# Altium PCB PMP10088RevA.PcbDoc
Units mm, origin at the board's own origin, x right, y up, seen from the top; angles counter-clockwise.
Board outline 78.74 x 52.07 mm, 2 copper layers (Top Layer, Bottom Layer), stack 1.575 mm thick; 38 components, 13 nets, 76 pads, 8 vias.
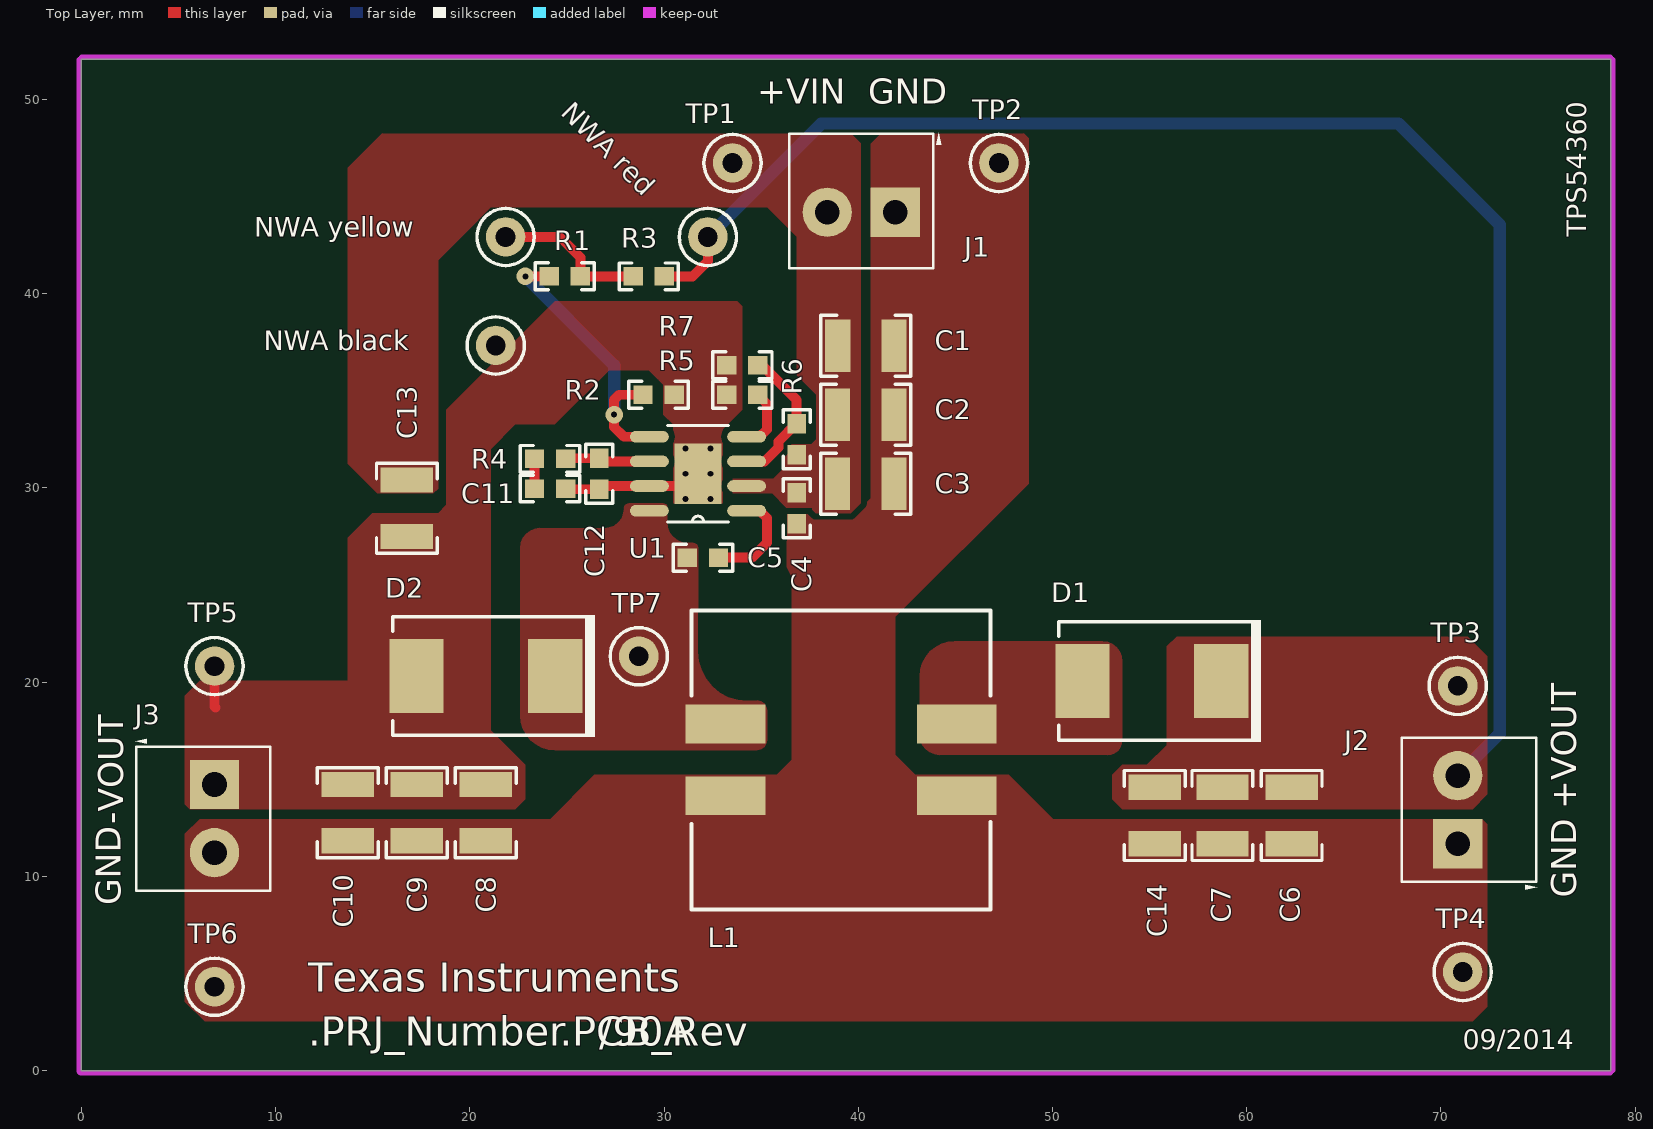
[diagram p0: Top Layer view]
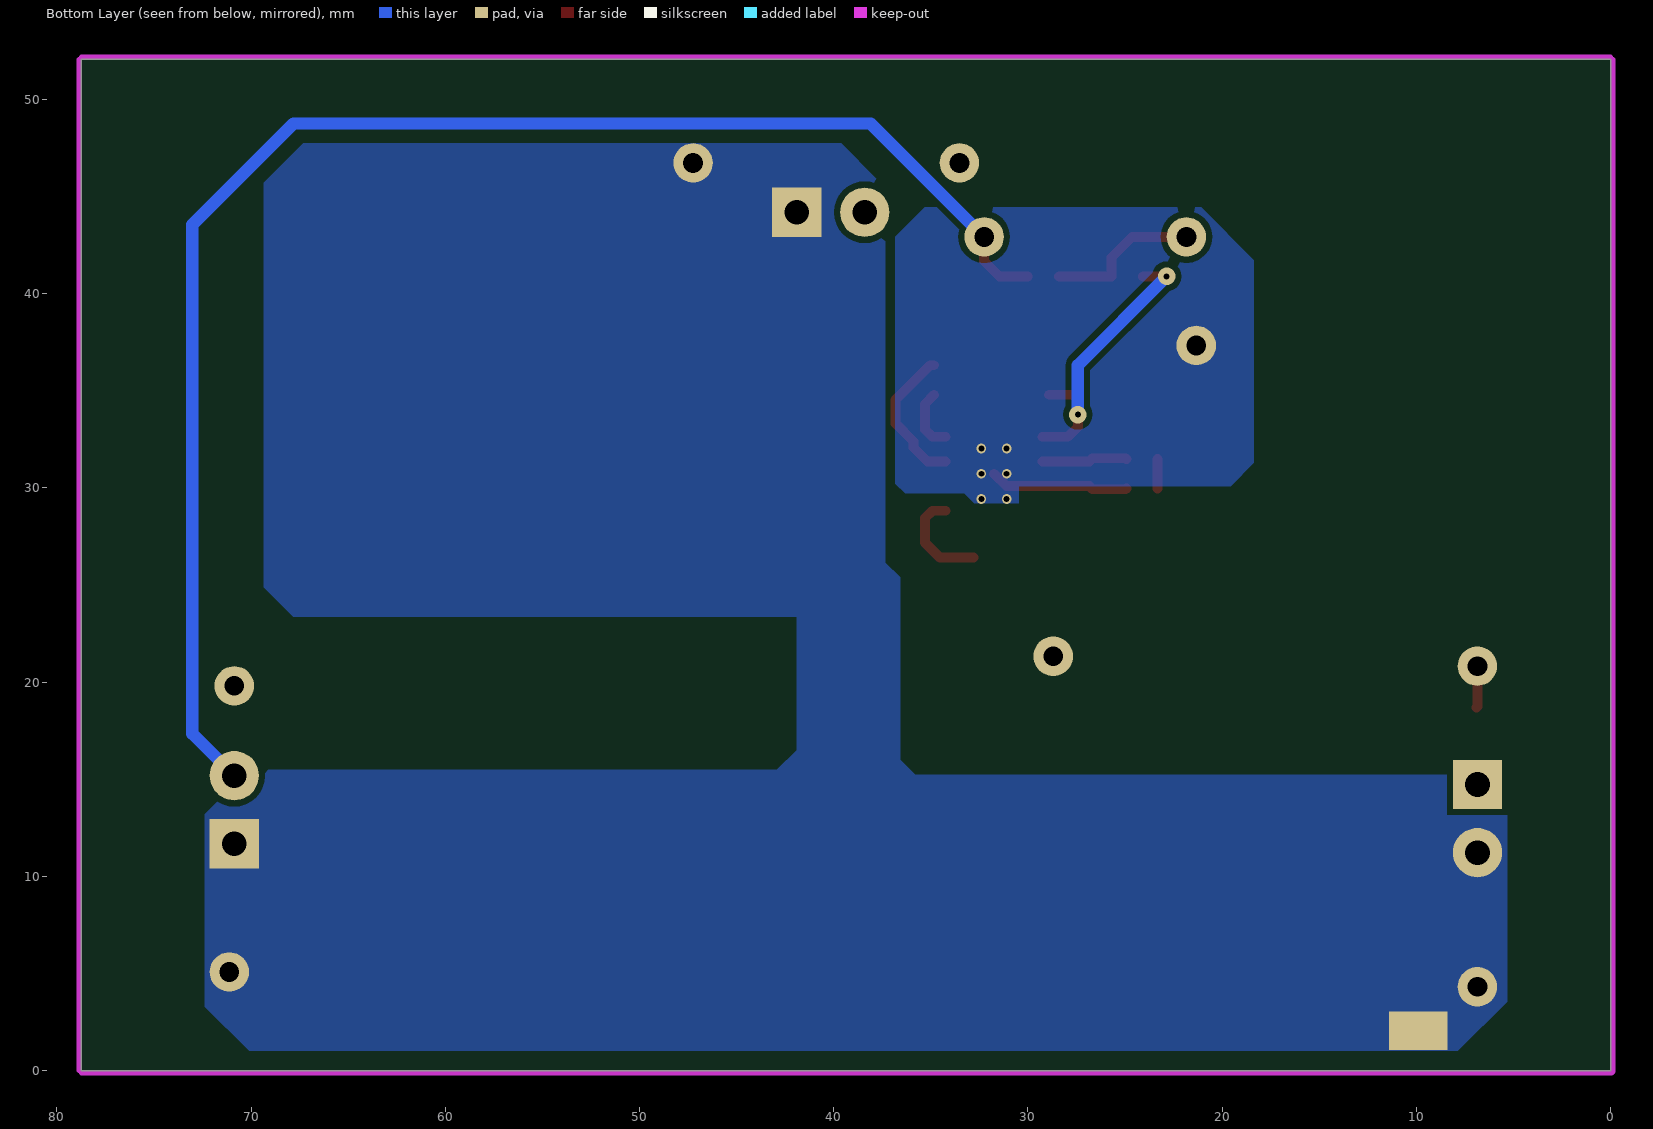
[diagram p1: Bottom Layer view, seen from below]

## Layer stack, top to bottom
Top Layer: signal copper 0.0356
Dielectric: core 1.5037, FR-4, Dk 4.8
Bottom Layer: signal copper 0.0356

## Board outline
0,0 78.74,0 78.74,52.07 0,52.07

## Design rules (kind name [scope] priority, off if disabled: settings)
AcuteAngle [All] p1: minimum=4.50000000000000E+0001 checktracksonly=FALSE
AssemblyTestPointUsage [All] p1: valid=2
Clearance Clearance_BoardEdge_MountingHoles [OnCopper and InComponentClass('Mounting Holes') vs IsKeepOut] p1: gap=1.016
Clearance Clearance_BoardEdge_Poly [OnCopper and InPoly vs IsKeepOut] p2: gap=0.635
Clearance Clearance_BoardEdge [OnCopper and Not InComponentClass('Logo') and not InComponentClass('FiducialMark') and not InRegion(1000,500,4000,800) and Not IsKeepout vs IsKeepOut] p3: gap=1
Clearance Clearance_Poly [InPolygon] p4: gap=0.32
Clearance [All] p5: gap=0.203
ComponentClearance ComponentClearance_Shunt [InComponentClass('Header') vs InComponentClass('Shunt')] p1: gap=0 collisioncheckmode=3 verticalgap=0 showdistances=FALSE
ComponentClearance ComponentClearance_Logo [InComponentClass('Logo')] p2: gap=1.27 collisioncheckmode=3 verticalgap=0.254 showdistances=FALSE
ComponentClearance ComponentClearance_ScrewToNut [(HasFootprint('NY PMS 440 0025 PH')) vs (HasFootprint('Keystone_1902C'))] p3: gap=0.127 collisioncheckmode=3 verticalgap=0.254 showdistances=FALSE
ComponentClearance ComponentClearance_MountingHoles [InComponentClass('Mounting Holes')] p4: gap=6.35 collisioncheckmode=3 verticalgap=2540 showdistances=FALSE
ComponentClearance ComponentClearance_SmallPassives [HasFootprint('0201*') or HasFootprint('0402*') or HasFootprint('0508') or HasFootprint('0603*') or HasFootprint('0612') or HasFootprint('0805*') or HasFootprint('0815*') or HasFootprint('0830*') or HasFootprint('1206*') or HasFootprint('1210*') or HasFootprint('1808*') or HasFootprint('1812*') or HasFootprint('1825*') or HasFootprint('2010*') or HasFootprint('2220*') or HasFootprint('2225*') or HasFootprint('2512*') or HasFootprint('2728*') or HasFootprint('3518*') vs HasFootprint('0201*') or HasFootprint('0402*') or HasFootprint('0508') or HasFootprint('0603*') or HasFootprint('0612') or HasFootprint('0805*') or HasFootprint('0815*') or HasFootprint('0830*') or HasFootprint('1206*') or HasFootprint('1210*') or HasFootprint('1808*') or HasFootprint('1812*') or HasFootprint('1825*') or HasFootprint('2010*') or HasFootprint('2220*') or HasFootprint('2225*') or HasFootprint('2512*') or HasFootprint('2728*') or HasFootprint('3518*')] p5: gap=0.508 collisioncheckmode=3 verticalgap=0.254 showdistances=FALSE
ComponentClearance ComponentClearance_THtoSMT [IsThruComponent vs IsSMTComponent] p6: gap=1.27 collisioncheckmode=3 verticalgap=0.762 showdistances=FALSE
ComponentClearance ComponentClearance_THtoTH [IsThruComponent vs IsThruComponent] p7: gap=1.5 collisioncheckmode=3 verticalgap=0.762 showdistances=FALSE
ComponentClearance [All] p8: gap=1.016 collisioncheckmode=3 verticalgap=0.254 showdistances=FALSE
DiffPairsRouting [All] p1: maxlimit=2.54 minlimit=0.254 mostfreqgap=0.254 maxuncoupledlength=25.4
FabricationTestPointUsage TestPointUsage [All] p1: valid=2 allowmultiple=FALSE
FabricationTestpoint Testpoint [All] p1: side=3 testpointundercomponent=TRUE minsize=1.016 maxsize=2.54 preferedsize=1.524 minholesize=0 maxholesize=1.016 preferedholesize=0.813 testpointgrid=0.025 allowsidetop=TRUE allowsidebottom=TRUE usegrid=TRUE gridtolerance=0
FanoutControl Fanout_LCC [IsLCC] p1: bgadir=Out bgaviamode=Centered fanoutstyle=Auto fanoutdirection=Alternating viagrid=0.025 // Fanout_LCC (Default Rule)
FanoutControl Fanout_BGA [IsBGA] p2: bgadir=Out bgaviamode=Centered fanoutstyle=Auto fanoutdirection=Alternating viagrid=0.025 // Fanout_BGA (Default Rule)
FanoutControl Fanout_Default [All] p4: bgadir=Out bgaviamode=Centered fanoutstyle=Auto fanoutdirection=Alternating viagrid=0.025 // Fanout_Default (Default Rule)
FanoutControl Fanout_Small [(CompPinCount < 5)] p5: bgadir=Out bgaviamode=Centered fanoutstyle=Auto fanoutdirection=OutThenIn viagrid=0.025 // Fanout_Small (Default Rule)
HoleSize [All] p1: absolutevalues=TRUE maxlimit=6.375 minlimit=0.3 maxpercent=80.000 minpercent=20.000
MinimumAnnularRing MinimumAnnularRing_ThermalPadVias [IsVia and InAnyComponent] p1: minimumring=0.15
MinimumAnnularRing [All] p2: minimumring=0.2
MinimumSolderMaskSliver MinimumSolderMaskSliver_Logo [InComponentClass('Logo') vs InComponentClass('Logo')] p1: minsoldermaskwidth=0.018
MinimumSolderMaskSliver [All] p2: minsoldermaskwidth=0.1
PlaneConnect [All] p1: planeconnectstyle=Relief reliefexpansion=0.254 reliefentries=4 reliefconductorwidth=0.254 reliefairgap=0.254
PolygonConnect [All] p1: connectstyle=Direct reliefconductorwidth=0.254 reliefentries=4 polygonreliefangle="90 Angle" airgapwidth=0.254
RoutingVias ThermalPadVias [IsVia and InAnyComponent] p1: holewidth=0.2 width=0.5 viastyle="Through Hole" minholewidth=0.3 minwidth=0.5 maxholewidth=0.33 maxwidth=0.6
RoutingVias [All] p2: holewidth=0.406 width=0.864 viastyle="Through Hole" minholewidth=0.3 minwidth=0.66 maxholewidth=1.016 maxwidth=1.651
SMDToCorner [All] p1: distance=30000
SilkToSilkClearance [All] p1: silktosilkclearance=0.127
SilkscreenOverComponentPads [All] p1: minsilkscreentomaskgap=0.127
SolderMaskExpansion [All] p1: expansion=0.05
Width [All] p1: maxlimit=2.54 minlimit=0.152 preferedwidth=0.254 checkconnectedcopper=TRUE
14 further rules are at their usual default settings.

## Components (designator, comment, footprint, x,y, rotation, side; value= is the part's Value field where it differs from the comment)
C1 "GRM32ER71H106KA12L" 1210 40.394,37.33 r0 top
C2 "GRM32ER71H106KA12L" 1210 40.386,33.774 r0 top
C3 "GRM32ER71H106KA12L" 1210 40.386,30.218 r0 top
C4 "GRM188R71H104KA93D" 0603 36.83,28.956 r270 top
C5 "GRM188R71H104KA93D" 0603 32.004,26.416 r180 top
C6 "GRM32ER71E226KE15L" 1210 62.309,13.138 r270 top
C7 "GRM32ER71E226KE15L" 1210 58.753,13.138 r270 top
C8 "GRM32ER71E226KE15L" 1210 20.828,13.286 r90 top
C9 "GRM32ER71E226KE15L" 1210 17.272,13.286 r90 top
C10 "GRM32ER71E226KE15L" 1210 13.716,13.286 r90 top
C11 "GRM188R71E224KA88D" 0603 24.13,29.972 r0 top
C12 "GRM188R71H681KA01D" 0603 26.67,30.734 r270 top
C13 "GRM32ER71H106KA12L" 1210 16.764,28.956 r270 top
C14 "GRM32ER71E226KE15L" 1210 55.273,13.138 r270 top
D1 "B360-13-F" SMC 55.118,20.066 r180 top
D2 "B360-13-F" SMC 20.828,20.32 r180 top
J1 "ED555/2DS" TERM_BLK_ED555-2DS 41.91,44.196 r180 top
J2 "ED555/2DS" TERM_BLK_ED555-2DS 70.866,11.684 r90 top
J3 "ED555/2DS" TERM_BLK_ED555-2DS 6.858,14.732 r270 top
L1 "MSD1583-333MEB" IND_MSD1583 39.116,16.002 r0 top
"NWA black" "5001" Keystone5001 21.336,37.338 r90 top
"NWA red" "5000" Keystone5000 32.258,42.926 r90 top
"NWA yellow" "5003" Keystone5003 21.844,42.926 r90 top
R1 "CRCW060356K2FKEA" 0603 24.892,40.894 r0 top
R2 "CRCW06031K96FKEA" 0603 29.718,34.798 r180 top
R3 "CRCW060349R9FKEA" 0603 29.21,40.894 r180 top
R4 "CRCW06034K42FKEA" 0603 24.13,31.496 r0 top
R5 "CRCW0603412KFKEA" 0603 34.036,34.798 r0 top
R6 "CRCW0603422KFKEA" 0603 36.83,32.512 r270 top
R7 "CRCW060349K9FKEA" 0603 34.036,36.322 r0 top
TP1 "5000" Keystone5000 33.528,46.736 r90 top
TP2 "5001" Keystone5001 47.244,46.736 r90 top
TP3 "5000" Keystone5000 70.866,19.812 r90 top
TP4 "5001" Keystone5001 71.12,5.08 r90 top
TP5 "5117" Keystone5117 6.858,20.828 r90 top
TP6 "5001" Keystone5001 6.858,4.318 r90 top
TP7 "5002" Keystone5002 28.702,21.336 r90 top
U1 "TPS54360DDA" DDA0008E_N 31.75,30.734 r180 top

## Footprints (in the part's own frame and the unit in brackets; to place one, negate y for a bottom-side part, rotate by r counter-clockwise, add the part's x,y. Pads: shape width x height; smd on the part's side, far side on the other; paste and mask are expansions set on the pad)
0603 [mm] "0603 from SM-752 data"
  rect 1x0.95 smd: 1(-0.8,0) 2(0.8,0)
  silkscreen extent -1.52,-0.69 1.52,0.69, body extent -0.87,-0.47 0.87,0.47, height 0.85
1210 [mm] "1210 from SM-752 data"
  rect 1.3x2.7 smd: 1(-1.45,0) 2(1.45,0)
  silkscreen extent -2.32,-1.57 2.32,1.57, body extent -1.7,-1.35 1.7,1.35, height 1.35
DDA0008E_N [mm]
  oval 2x0.6 smd: 1(-2.5,1.905) 2(-2.5,0.635) 3(-2.5,-0.635) 4(-2.5,-1.905) 5(2.5,-1.905) 6(2.5,-0.635) 7(2.5,0.635) 8(2.5,1.905)
  rect 2.4x3.1 smd: 9(0,0)
  silkscreen extent -1.58,-2.49 1.58,2.49, body extent -2.98,-2.45 2.98,2.45, height 1.5
IND_MSD1583 [mm] "COILCRAFT"
  rect 4.1x2 smd: 1(-5.95,1.85) 2(-5.95,-1.85) 3(5.95,-1.85) 4(5.95,1.85)
  silkscreen extent -7.7,-7.7 7.7,7.7, body extent -7.55,-7.55 7.55,7.55, height 8.6
Keystone5000 [mil] "For Keystone 500x miniature loop terminals"
  round 80 hole 40: 1(0,0)
  silkscreen extent -58,-58 58,58, body extent -49,-49 49,49, height 182
Keystone5001 [mil] "For Keystone 500x miniature loop terminals"
  round 80 hole 40: 1(0,0)
  silkscreen extent -58,-58 58,58, body extent -49,-49 49,49, height 182
Keystone5002 [mil] "For Keystone 500x miniature loop terminals"
  round 80 hole 40: 1(0,0)
  silkscreen extent -58,-58 58,58, body extent -49,-49 49,49, height 182
Keystone5003 [mil] "For Keystone 500x miniature loop terminals"
  round 80 hole 40: 1(0,0)
  silkscreen extent -58,-58 58,58, body extent -49,-49 49,49, height 182
Keystone5117 [mil] "For Keystone 500x miniature loop terminals"
  round 80 hole 40: 1(0,0)
  silkscreen extent -58,-58 58,58, body extent -49,-49 49,49, height 182
SMC [mil] "Molded Diode, 2-Leads, Body 6.9x5.8mm, IPC Medium Density, based on OnSemi component dimensions and land patterns"
  rect 110x150 smd: 1(-140.49,0) 2(140.49,0)
  silkscreen extent -221,-124 189,123, body extent -156,-116 156,116, height 91
TERM_BLK_ED555-2DS [mil]
  rect 100x100 hole 50: 1(0,0)
  round 100 hole 50: 2(138,0)
  silkscreen extent -93,-161 215,113, body extent -69,-150 207,106, height 323

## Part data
C1 C2 C3 C13: "CAP, CERM, 10uF, 50V, +/-10%, X7R, 1210"
C4 C5: "CAP, CERM, 0.1uF, 50V, +/-10%, X7R, 0603"
C6 C7 C8 C9 C10 C14: "CAP, CERM, 22uF, 25V, +/-10%, X7R, 1210"
C11: "CAP, CERM, 0.22uF, 25V, +/-10%, X7R, 0603"
C12: "CAP, CERM, 680pF, 50V, +/-10%, X7R, 0603"
D1 D2: "Diode, Schottky, 60V, 3A, SMC"
J1 J2 J3: "Terminal Block, 6A, 3.5mm Pitch, 2-Pos, TH"
L1: library part MSD1583-473MEB, "Coupled inductor, 33uH, 2.16A, 0.083 ohm, +/-20%, SMD"
"NWA black" TP2 TP4 TP6: "Test Point, Miniature, Black, TH"
"NWA red" TP1 TP3: "Test Point, Miniature, Red, TH"
"NWA yellow": "Test Point, Miniature, Orange, TH"
R1: "RES, 56.2k ohm, 1%, 0.1W, 0603"
R2: "RES, 1.96k ohm, 1%, 0.1W, 0603"
R3: "RES, 49.9 ohm, 1%, 0.1W, 0603"
R4: "RES, 4.42k ohm, 1%, 0.1W, 0603"
R5: "RES, 412k ohm, 1%, 0.1W, 0603"
R6: "RES, 422k ohm, 1%, 0.1W, 0603"
R7: "RES, 49.9k ohm, 1%, 0.1W, 0603"
TP5: "Test Point, Miniature, Blue, TH"
TP7: "Test Point, Miniature, White, TH"
U1: "60 V Input, 3.5 A, Step Down DC-DC Converter with Eco-mode, DDA0008E"

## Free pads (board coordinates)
  rect 0x0 / inner round 0 / far side rect 3x2 all layers, no hole: 0(9.906,2.057)

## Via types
v1: diameter 0.5, hole 0.3, Top Layer to Bottom Layer, tented top, 6 vias
v2: diameter 0.9, hole 0.3, Top Layer to Bottom Layer, tented both sides, 2 vias

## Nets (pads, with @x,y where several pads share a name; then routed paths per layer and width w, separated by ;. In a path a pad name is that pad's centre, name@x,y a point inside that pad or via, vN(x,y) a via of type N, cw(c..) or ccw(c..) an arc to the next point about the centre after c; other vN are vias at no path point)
+12V: "NWA red.1" C6.1 C7.1 C14.1 D1.1 J2.2 R3.1 TP3.1 | length 78.4
  Top Layer w0.508: R3.1 31.468,40.894 32.258,41.684 32.258,42.926
  Bottom Layer w0.635: 32.258,42.926 38.1,48.768 67.818,48.768 73.025,43.561 73.025,17.348 J2.2
GND: C1.2 C2.2 C3.2 C4.2 C6.2 C7.2 C8.1 C9.1 C10.1 C14.2 J1.1 J2.1 J3.2 L1.2 L1.3 pad.0 TP2.1 TP4.1 TP6.1
NetC1_1: C1.1 C2.1 C3.1 C4.1 C13.1 J1.2 R6.2 TP1.1 U1.2
NetC5_1: C5.1 U1.1 | length 5.3
  Top Layer w0.508: C5.1 34.544,26.416 35.306,27.178 35.306,28.448 34.925,28.829 U1.1
NetC5_2: C5.2 D2.1 L1.1 TP7.1 U1.8
NetC8_2: "NWA black.1" C8.2 C9.2 C10.2 C11.2 C12.2 C13.2 D2.2 J3.1 R2.1 R5.1 R7.1 TP5.1 U1.7 U1.9 | length 9.3
  Top Layer w0.508: TP5.1 6.858,18.745 6.909,18.694 ; C11.2 24.968,29.934 C12.2 26.835,30.099 U1.7 31.115,30.099 U1.9
  other v1: 31.1,29.434 32.4,29.434 31.1,30.734 32.4,30.734 31.1,32.034 32.4,32.034
NetC11_1: C11.1 R4.1 | length 1.5
  Top Layer w0.508: C11.1 R4.1
NetC12_1: C12.1 R4.2 U1.6 | length 4.4
  Top Layer w0.508: R4.2 24.968,31.534 C12.1 26.835,31.369 U1.6
NetD1_2: D1.2 L1.4
"NetNWA yellow_1": "NWA yellow.1" R1.2 R3.2 | length 8
  Top Layer w0.508: 21.844,42.926 24.638,42.926 25.692,41.872 R1.2 R3.2
NetR1_1: R1.1 R2.2 U1.5 | length 15.3
  Top Layer w0.508: v2(22.86,40.894) R1.1 ; R2.2 27.686,34.798 27.432,34.544 v2(27.432,33.782) 27.432,33.138 27.931,32.639 U1.5
  Bottom Layer w0.635: v2(22.86,40.894) 27.432,36.322 v2(27.432,33.782)
NetR5_2: R5.2 U1.4 | length 3.2
  Top Layer w0.508: U1.4 34.925,32.639 35.306,33.02 35.306,34.328 R5.2
NetR6_1: R6.1 R7.2 U1.3 | length 7.5
  Top Layer w0.508: U1.3 35.179,31.369 35.898,32.088 35.898,32.401 R6.1@36.808,33.312 ; R7.2 35.052,36.322 36.83,34.544 R6.1

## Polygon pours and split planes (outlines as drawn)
NetC8_2 on Top Layer "Top Layer-VOUTN" (solid, remove dead copper, pour order 2): 30.48,29.21 30.48,33.274 29.972,33.782 29.972,35.306 29.21,36.068 27.178,36.068 24.384,33.274 22.352,33.274 21.082,32.004 21.082,17.526 22.86,15.748 22.86,13.97 22.352,13.462 5.588,13.462 5.334,13.716 5.334,19.304 6.096,20.066 13.716,20.066 13.716,27.432 14.986,28.702 18.364,28.702 18.796,29.134 18.796,34.036 24.384,39.624 33.782,39.624 34.036,39.37 34.036,34.036 33.02,33.02 33.02,29.21
NetC5_2 on Top Layer "Top Layer-swp1" (solid, remove dead copper, pour order 4): 34.798,16.51 24.384,16.51 cw(c24.384,18.288) 22.606,18.288 22.606,26.924 cw(c23.622,26.924) 23.622,27.94 26.924,27.94 ccw(c26.924,28.956) 27.94,28.956 cw(c28.194,28.956) 28.194,29.21 29.972,29.21 cw(c29.972,29.009) 30.173,29.009 30.173,28.245 ccw(c31.24,28.245) 31.24,27.178 31.496,27.178 cw(c31.496,26.924) 31.75,26.924 31.75,25.691 31.75,21.59 ccw(c34.29,21.59) 34.29,19.05 34.798,19.05 cw(c34.798,18.542) 35.306,18.542 35.306,17.018 cw(c34.798,17.018) 34.798,16.51
NetC1_1 on Top Layer "Top Layer-vin1" (solid, remove dead copper, pour order 6): 36.83,45.72 39.37,45.72 39.878,45.212 40.132,44.958 40.132,29.21 39.624,28.702 37.846,28.702 37.809,28.702 37.555,28.956 36.355,28.956 36.322,28.956 35.56,29.718 33.528,29.718 33.528,30.48 35.623,30.48 36.105,30.962 36.105,32.004 36.105,32.008 36.355,32.258 37.592,32.258 37.846,32.512 37.846,32.766 37.846,34.798 36.83,35.814
NetC1_1 on Top Layer "Top Layer-vin C13" (solid, remove dead copper, pour order 8): 18.114,29.718 15.24,29.718 13.716,31.242 13.716,46.482 15.494,48.26 15.519,48.235 39.37,48.235 39.649,48.235 40.132,47.752 40.132,42.926 36.83,42.926 35.306,44.45 21.082,44.45 19.812,43.18 18.364,41.732 18.364,29.972
NetD1_2 on Top Layer "Top Layer-sws1" (solid, remove dead copper, pour order 10): 43.18,17.272 43.18,20.32 cw(c44.958,20.32) 44.958,22.098 52.578,22.098 cw(c52.578,21.082) 53.594,21.082 53.594,17.018 cw(c52.832,17.018) 52.832,16.256 44.196,16.256 cw(c44.196,17.272) 43.18,17.272
+12V on Top Layer "Top Layer-voutP" (solid, remove dead copper, pour order 12): 55.88,21.844 55.88,16.764 54.864,15.748 53.594,15.748 53.086,15.24 53.086,13.97 53.594,13.462 71.628,13.462 72.39,14.224 72.39,21.336 71.374,22.352 56.388,22.352
GND on Top Layer "Top Layer-gnd1" (solid, remove dead copper, pour order 14): 5.334,12.192 5.334,3.556 6.35,2.54 71.628,2.54 72.39,3.302 72.39,12.7 72.136,12.954 50.038,12.954 47.752,15.24 42.926,15.24 41.91,16.256 41.91,23.368 48.768,30.226 48.768,48.006 48.514,48.26 48.489,48.235 41.148,48.235 40.64,47.727 40.64,29.464 39.878,28.702 36.355,28.702 36.322,25.908 36.576,25.4 36.576,16.002 35.814,15.24 26.416,15.24 24.13,12.954 6.096,12.954
NetC8_2 on Bottom Layer "Bottom Layer-voutn" (solid, remove dead copper, pour order 16): 30.48,29.21 30.48,30.099 19.571,30.099 18.364,31.306 18.364,41.732 21.082,44.45 35.306,44.45 36.83,42.926 36.83,30.226 36.322,29.718 33.274,29.718 32.766,29.21
GND on Bottom Layer "bottom Layer-gnd" (solid, remove dead copper, pour order 18): 5.334,3.556 7.874,1.016 70.104,1.016 72.39,3.302 72.39,13.208 70.104,15.494 42.926,15.494 41.91,16.51 41.91,23.368 67.818,23.368 69.342,24.892 69.342,45.72 67.31,47.752 39.624,47.752 37.338,45.466 37.338,26.162 36.576,25.4 36.576,16.002 35.814,15.24 7.112,15.24 5.334,13.462

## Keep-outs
Keep-Out Layer:
  lines w0.254: -0.127,52.07 -0.127,0 ; 0,52.197 78.74,52.197 ; 78.74,-0.127 0,-0.127 ; 78.867,0 78.867,52.07 ; -0.127,0 ccw(c0,0) 0,-0.127 ; -0.127,0 ccw(c0,0) 0,-0.127 ; -0.127,0 ccw(c0,0) 0,-0.127 ; -0.127,0 ccw(c0,0) 0,-0.127 ; -0.127,0 ccw(c0,0) 0,-0.127 ; -0.127,0 ccw(c0,0) 0,-0.127 ; -0.127,87.63 cw(c0,87.63) 0,87.757 ; -0.127,87.63 cw(c0,87.63) 0,87.757 ; -0.127,87.63 cw(c0,87.63) 0,87.757 ; -0.127,87.63 cw(c0,87.63) 0,87.757 ; -0.127,87.63 cw(c0,87.63) 0,87.757 ; -0.127,87.63 cw(c0,87.63) 0,87.757 ; 125.73,-0.127 ccw(c125.73,0) 125.857,0 ; 125.73,-0.127 ccw(c125.73,0) 125.857,0 ; 125.73,-0.127 ccw(c125.73,0) 125.857,0 ; 125.73,-0.127 ccw(c125.73,0) 125.857,0 ; 125.73,-0.127 ccw(c125.73,0) 125.857,0 ; 125.73,-0.127 ccw(c125.73,0) 125.857,0 ; 125.73,87.757 cw(c125.73,87.63) 125.857,87.63 ; 125.73,87.757 cw(c125.73,87.63) 125.857,87.63 ; 125.73,87.757 cw(c125.73,87.63) 125.857,87.63 ; 125.73,87.757 cw(c125.73,87.63) 125.857,87.63 ; 125.73,87.757 cw(c125.73,87.63) 125.857,87.63 ; 125.73,87.757 cw(c125.73,87.63) 125.857,87.63
  text ".Layer_Name" at 14.656,-21.806 h1.52

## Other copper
Top Layer:
  text ".Layer_Name" at 14.656,-21.806 h1.52
Bottom Layer:
  text ".Layer_Name" at 14.656,-21.806 h1.52

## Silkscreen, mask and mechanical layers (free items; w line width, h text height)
Top Overlay:
  text "+VIN" at 34.798,49.784 h1.3
  text "GND" at 40.513,49.784 h1.3
  text "TPS54360" at 77.495,42.926 h1.02 r90
  text "+VOUT" at 76.962,13.462 h1.3 r90
  text "-VOUT" at 2.159,12.7 h1.3 r90
  text "GND" at 76.962,8.89 h1.3 r90
  text "GND" at 2.032,8.509 h1.3 r90
  text "Texas Instruments" at 11.684,4.064 h1.5
  text ".PRJ_Number" at 11.684,1.27 h1.5
  text ".PCB_Rev" at 24.638,1.27 h1.5
  text "/90A" at 26.67,1.27 h1.5
  text "09/2014" at 71.12,1.092 h1.02
  text ".Layer_Name" at 14.656,-21.806 h1.52
Bottom Overlay:
  text ".Layer_Name" at 14.656,-21.806 h1.52
Top Paste:
  text ".Layer_Name" at 14.656,-21.806 h1.52
Bottom Paste:
  text ".Layer_Name" at 14.656,-21.806 h1.52
Top Solder:
  text ".Layer_Name" at 14.656,-21.806 h1.52
  text ".Layer_Name" at 14.656,-21.806 h1.52
Bottom Solder:
  text "/90A" at 44.196,1.27 h1.5
  text ".PCB_Rev" at 46.228,1.27 h1.5
  text ".PRJ_Number" at 58.42,1.27 h1.5
  text ".Layer_Name" at 14.656,-21.806 h1.52
Drill Guide:
  text ".Layer_Name" at 14.656,-21.806 h1.52
M1 Board Outline:
  the board outline again, w0.254
  text ".Layer_Name" at 14.656,-21.806 h1.52
M2 Board Dimensions:
  rectangle: 3.162,-10.427 12.687,-7.252
  rectangle: -0.013,-7.252 3.162,-4.077
  lines w0.178: -0.013,-7.252 25.387,-7.252 ; 3.162,-10.427 3.162,-4.077 ; 6.337,-10.427 6.337,-4.077 ; 12.687,-10.427 12.687,-4.077 ; 19.037,-10.427 19.037,-4.077 ; -0.013,-10.427 -0.013,-4.077 25.387,-4.077 25.387,-10.427 -0.013,-10.427
  lines w0.254: -0.013,-12.078 -0.013,-11.57 ; 1.511,-12.332 -0.013,-11.824 ; 1.511,-11.316 -0.013,-11.824 ; 6.187,-11.824 -0.013,-11.824 ; 19.188,-11.824 25.387,-11.824 ; 23.863,-12.332 25.387,-11.824 ; 23.863,-11.316 25.387,-11.824 ; 25.387,-12.078 25.387,-11.57
  text "25.4 (mm)" at 6.441,-12.738 h1.52
  text ".Layer_Name" at 14.656,-21.806 h1.52
M3 3D STEP Top:
  text ".Layer_Name" at 14.656,-21.806 h1.52
M4 3D STEP Bottom:
  text ".Layer_Name" at 14.656,-21.806 h1.52
M5 Assembly Top:
  lines w0.254: -7.417,-23.626 160.223,-23.626 ; -7.417,-18.462 160.274,-18.462 ; -7.417,-13.297 -7.417,-28.791 94.31,-28.791 160.274,-28.791 160.274,-13.297 -7.404,-13.297 -7.404,-28.791 32.614,-28.791 ; 55.194,-28.791 55.194,-13.297 ; 87.376,-18.462 87.376,-13.297 ; 108.712,-18.462 108.712,-13.297 ; 124.511,-28.956 124.511,-23.804
  text "COMPONENTS MARKED 'DNP' SHOULD NOT BE POPULATED." at 29.299,-8.09 h1.52
  text "ASSEMBLY VARIANT:" at 29.286,-11.024 h1.52
  text ".VariantName" at 55.601,-11.024 h1.52
  text "PCB VIEWED FROM TOP SIDE" at -5.804,-16.654 h1.52
  text "BOARD #:" at 57.099,-16.654 h1.52
  text ".PRJ_Number" at 70.955,-16.654 h1.52
  text "REV:" at 92.405,-16.654 h1.52
  text ".PCB_Rev" at 99.809,-16.654 h1.52
  text "SVN REV:" at 113.69,-16.654 h1.52
  text ".VersionControl_RevNumber" at 126.543,-16.654 h1.52
  text "IGNORE ->" at -5.804,-21.806 h1.52
  text "PLOT NAME =" at -5.804,-27.034 h1.52
  text ".plot_File_Name" at 14.656,-27.034 h1.52
  text "GENERATED    :" at 57.15,-27.034 h1.52
  text ".Print_Date" at 79.235,-27.034 h1.52
  text ".Print_Time" at 97.752,-27.034 h1.52
  text "TEXAS INSTRUMENTS" at 129.87,-27.034 h1.52
M6 Assembly Bottom:
  lines w0.254: -7.429,-18.474 160.261,-18.474 ; -7.379,-23.639 160.261,-23.639 ; 28.334,-28.969 28.334,-23.817 ; 44.133,-18.474 44.133,-13.31 ; 65.468,-18.474 65.468,-13.31 ; 97.65,-28.804 97.65,-13.31 ; 120.231,-28.804 160.249,-28.804 160.249,-13.31 -7.429,-13.31 -7.429,-28.804 58.534,-28.804 160.261,-28.804 160.261,-13.31
  text "COMPONENTS MARKED 'DNP' SHOULD NOT BE POPULATED." at 154.991,-8.077 h1.52
  text ".VariantName" at 128.473,-11.024 h1.52
  text "ASSEMBLY VARIANT:" at 154.864,-11.024 h1.52
  text ".VersionControl_RevNumber" at 26.302,-16.667 h1.52
  text "SVN REV:" at 39.154,-16.667 h1.52
  text ".PCB_Rev" at 53.035,-16.667 h1.52
  text "REV:" at 60.439,-16.667 h1.52
  text ".PRJ_Number" at 81.89,-16.667 h1.52
  text "BOARD #:" at 95.745,-16.667 h1.52
  text "PCB VIEWED FROM BOTTOM SIDE" at 158.648,-16.667 h1.52
  text "IGNORE ->" at 64.715,-21.806 h1.52
  text "TEXAS INSTRUMENTS" at 22.974,-27.047 h1.52
  text ".Print_Time" at 55.093,-27.047 h1.52
  text ".Print_Date" at 73.609,-27.047 h1.52
  text "GENERATED    :" at 95.694,-27.047 h1.52
  text ".plot_File_Name" at 138.189,-27.047 h1.52
  text "PLOT NAME =" at 158.648,-27.047 h1.52
M9 Title Sheet:
  drawing of 57 lines, arcs and shapes, not listed
  text "1" at 18.792,204.127 h1.78
  text "2" at 82.182,204.127 h1.78
  text "3" at 145.411,204.127 h1.78
  text "4" at 209.08,204.127 h1.78
  text "5" at 272.555,204.127 h1.78
  text "6" at 336.182,204.127 h1.78
  text "A" at -10.579,175.095 h1.78
  text "A" at 365.341,175.095 h1.78
  text "B" at -10.579,114.643 h1.78
  text "B" at 365.341,114.643 h1.78
  text "C" at -10.579,54.318 h1.78
  text "C" at 365.341,54.318 h1.78
  text "PROJECT TITLE:" at 288.125,7.048 h1.14
  text ".PRJ_Title" at 289.395,3.662 h1.78
  text "DESIGNED FOR:" at 288.125,-0.597 h1.14
  text ".PRJ_Customer" at 289.395,-4.153 h1.78
  text "D" at -10.579,-5.88 h1.78
  text "D" at 365.341,-5.88 h1.78
  text "FILE NAME:" at 288.125,-8.217 h1.14
  text ".PCB_File_Name_No_Path" at 289.395,-11.265 h1.78
  text "Texas Instruments (TI) and/or its licensors do not warrant the accuracy or completeness of this specification" at 161.9,-15.376 h1.14
  text "ENGINEER:" at 288.125,-15.583 h1.14
  text "LAYOUT BY:" at 326.352,-15.583 h1.14
  text "or any information contained therein. TI and/or its licensors do not warrant that this design will meet" at 160.757,-18.237 h1.14
  text ".PRJ_Engineer" at 289.395,-19.52 h1.78
  text ".PCB_Layout" at 327.635,-19.52 h1.78
  text "the specifications, will be suitable for your application or fit for any particular purpose, or will operate in" at 160.757,-21.099 h1.14
  text ".Layer_Name" at 14.656,-21.806 h1.52
  text "ALTIUM DESIGNER VERSION:" at 326.352,-23.457 h1.14
  text "an implementation. TI and/or its licensors do not warrant that the design is production worthy. You should" at 160.757,-23.961 h1.14
  text "completely validate and test your design implementation to confirm the system functionality for your application." at 161.9,-26.822 h1.14
  text ".print_Scale" at 289.395,-26.843 h1.78
  text ".Application_BuildNumber" at 327.635,-26.843 h1.78
  text "1" at 18.792,-32.093 h1.78
  text "2" at 82.182,-32.093 h1.78
  text "3" at 145.411,-32.093 h1.78
  text "4" at 209.08,-32.093 h1.78
  text "5" at 272.555,-32.093 h1.78
  text "6" at 336.182,-32.093 h1.78
M10 Fab Notes:
  drawing of 212 lines, arcs and shapes, not listed
  text "DESIGN INFORMATION" at 314.478,172.974 h1.52
  text "(REFER ALSO ARRAY/PANEL PROFILING INFORMATION)" at 305.294,168.866 h1.52
  text "BOARD SIZE" at 287.87,168.758 h1.52
  text "3450MIL" at 299.613,165.511 h1.52
  text "X" at 312.457,165.511 h1.52
  text "4950MIL" at 318.333,165.511 h1.52
  text "Number of Layers :" at 298.106,160.503 h1.52
  text "2" at 325.914,160.249 h1.52
  text "MIN. TRACK WIDTH:" at 298.106,156.972 h1.52
  text "8" at 325.951,156.972 h1.52
  text "MIL" at 329.881,156.972 h1.52
  text "MIN. CLEARANCE:" at 298.106,153.619 h1.52
  text "8" at 325.951,153.619 h1.52
  text "MIL" at 329.881,153.619 h1.52
  text "MIN. VIA PAD SIZE:" at 298.106,150.266 h1.52
  text "24" at 325.189,150.266 h1.52
  text "MIL" at 329.881,150.266 h1.52
  text "0.05mm (2MIL)" at 315.759,146.667 h1.52
  text "MINIMUM ANNULAR RING" at 289.744,146.558 h1.52
  text "EXTERNAL" at 333.742,146.558 h1.52
  text "PER" at 294.824,143.561 h1.52
  text "IPC-D-275 CLASS 2 LEVEL C" at 300.412,143.561 h1.52
  text "MIL, HOLES" at 338.213,140.709 h1.52
  text "+/-" at 328.244,140.691 h1.52
  text "+/-" at 349.936,140.691 h1.52
  text "REGISTRATION TOLERANCES:" at 289.744,140.564 h1.52
  text "METAL" at 320.218,140.564 h1.52
  text "5" at 334.853,140.564 h1.52
  text "3" at 356.012,140.564 h1.52
  text "MIL" at 358.964,140.564 h1.52
  text "MATERIAL:" at 287.844,135.243 h1.52
  text "FR-4 High Tg" at 312.9,131.679 h1.52
  text "FR-408" at 298.538,131.461 h1.52
  text "X" at 309.003,131.461 h1.52
  text "OTHER" at 336.333,131.461 h1.52
  text "62 MIL (1.6mm) +/-10%" at 306.668,127.328 h1.52
  text "THICKNESS:" at 289.744,127.219 h1.52
  text "X" at 303.413,127.219 h1.52
  text "OTHER" at 339.305,127.219 h1.52
  text "TOLERANCE:" at 289.744,123.206 h1.52
  text "X" at 311.062,123.206 h1.52
  text "ANSI IPC-6012 TYPE 3 CLASS 2" at 315.81,123.206 h1.52
  text "OTHER +/-" at 315.81,119.244 h1.52
  text "BOW & TWIST:" at 289.744,115.256 h1.52
  text "X" at 311.062,115.256 h1.52
  text "ANSI IPC-6012 TYPE 3 CLASS 2" at 315.81,115.256 h1.52
  text "OTHER +/-" at 315.81,111.23 h1.52
  text "COPPER THICKNESS (FINISHED):" at 287.844,107.788 h1.52
  text "1.4MIL (1oz)" at 310.196,103.909 h1.52
  text "2MIL (1.4oz)" at 329.678,103.909 h1.52
  text "2.8MIL (2oz)" at 348.144,103.909 h1.52
  text "OUTER:" at 296.912,103.801 h1.52
  text "X" at 306.934,103.784 h1.52
  text "1.4MIL (1oz)" at 310.196,99.922 h1.52
  text "2.8MIL (2oz)" at 329.678,99.922 h1.52
  text "N/A" at 348.132,99.931 h1.52
  text "INNER SIGNAL:" at 289.57,99.813 h1.52
  text "X" at 306.97,99.813 h1.52
  text "DRILLING:" at 287.844,96.282 h1.52
  text "REFERENCE:" at 289.744,93.31 h1.52
  text "X" at 306.209,93.31 h1.52
  text "AS SHOWN" at 310.958,93.31 h1.52
  text "X" at 329.094,93.31 h1.52
  text "NC_DRILL FILES" at 332.574,93.31 h1.52
  text "PTH MIN COPPER THICKNESS:" at 289.744,89.297 h1.52
  text "X" at 324.039,89.297 h1.52
  text "1MIL" at 327.519,89.297 h1.52
  text "OTHER" at 340.143,89.297 h1.52
  text "BOARD FINISH:" at 287.844,85.259 h1.52
  text "SILKSCREEN:" at 291.787,82.261 h1.52
  text "X" at 315.886,82.261 h1.52
  text "TOP" at 319.086,82.261 h1.52
  text "X" at 328.84,82.261 h1.52
  text "BOTTOM" at 332.066,82.261 h1.52
  text "SILKSCREEN COLOR:" at 291.787,78.02 h1.52
  text "X" at 315.86,78.02 h1.52
  text "WHITE" at 319.086,78.02 h1.52
  text "OTHER" at 332.066,78.02 h1.52
  text "SOLDER RESIST COLOR:" at 291.787,73.702 h1.52
  text "X" at 306.208,69.658 h1.52
  text "GREEN" at 309.434,69.658 h1.52
  text "BLUE" at 324.446,69.658 h1.52
  text "OTHER" at 338.111,69.658 h1.52
  text "IMMERSION GOLD (ENIG)" at 314.794,64.87 h1.52
  text "ENEPIG" at 348.767,64.786 h1.52
  text "SURFACE FINISH:" at 287.844,64.761 h1.52
  text "X" at 310.045,64.761 h1.52
  text "IMM. TIN/SILVER OR EQUIV" at 296.215,60.773 h1.52
  text "OTHER" at 332.574,60.773 h1.52
  text "ARRAY/PANEL:" at 287.844,56.226 h1.52
  text "CUT AND TRIM PER MECH LAYER 1" at 314.794,56.118 h1.52
  text "N.C. ROUTE" at 314.794,52.264 h1.52
  text "X" at 332.04,52.264 h1.52
  text "V. SCORE" at 336.79,52.264 h1.52
  text "CERTIFICATION:" at 287.844,48.784 h1.52
  text "MATERIALS AND WORKMANSHIP FOR ALL PCBS" at 306.259,48.784 h1.52
  text "TO MEET OR EXCEED THE REQUIREMENTS OF:" at 306.259,46.295 h1.52
  text "X" at 296.773,42.828 h1.52
  text "ANSI IPC-A-600F CLASS ->" at 300.303,42.828 h1.52
  text "X" at 341.935,42.828 h1.52
  text "2" at 344.956,42.828 h1.52
  text "1" at 336.955,42.79 h1.52
  text "3" at 353.948,42.79 h1.52
  text "X" at 296.825,38.777 h1.52
  text "UL 94V-0" at 300.303,38.777 h1.52
  text "X" at 317.45,38.777 h1.52
  text "RoHS" at 320.928,38.777 h1.52
  text "OTHER" at 337.296,38.777 h1.52
  text "PER ORDER" at 347.381,38.777 h1.52
  text "ADDITIONAL REQUIREMENTS:" at 287.844,35.195 h1.52
  text "MICROSECTION:" at 289.744,32.274 h1.52
  text "YES" at 312.749,32.274 h1.52
  text "REQUIRED" at 334.631,28.308 h1.52
  text "BARE BOARD ELEC. TEST:" at 289.744,28.236 h1.52
  text "NONE" at 322.909,28.236 h1.52
  text "X" at 331.405,28.236 h1.52
  text "PER ORDER" at 349.668,28.236 h1.52
  text "MANUFACTURER'S UL:" at 289.744,24.248 h1.52
  text "RAIL" at 319.353,24.139 h1.52
  text "METAL" at 331.845,24.139 h1.52
  text "X" at 341.376,24.13 h1.52
  text "SILK" at 344.842,24.139 h1.52
  text ".Layer_Name" at 14.656,-21.806 h1.52
M11 Gerber Information:
  lines w0.254: -7.417,-23.626 160.223,-23.626 ; -7.417,-18.462 160.274,-18.462 ; -7.417,-13.297 -7.417,-28.791 94.31,-28.791 160.274,-28.791 160.274,-13.297 -7.404,-13.297 -7.404,-28.791 32.614,-28.791 ; 55.194,-28.791 55.194,-13.297 ; 87.376,-18.462 87.376,-13.297 ; 108.712,-18.462 108.712,-13.297 ; 124.511,-28.956 124.511,-23.804
  text "ALL ARTWORK VIEWED FROM TOP SIDE" at -5.804,-16.654 h1.52
  text "BOARD #:" at 57.099,-16.654 h1.52
  text ".PRJ_Number" at 70.955,-16.654 h1.52
  text "REV:" at 92.405,-16.654 h1.52
  text ".PCB_Rev" at 99.809,-16.654 h1.52
  text "SVN REV:" at 113.69,-16.654 h1.52
  text ".VersionControl_RevNumber" at 126.543,-16.654 h1.52
  text "LAYER NAME =" at -5.804,-21.806 h1.52
  text "PLOT NAME =" at -5.804,-27.034 h1.52
  text ".plot_File_Name" at 14.656,-27.034 h1.52
  text "GENERATED    :" at 57.15,-27.034 h1.52
  text ".Print_Date" at 79.235,-27.034 h1.52
  text ".Print_Time" at 97.752,-27.034 h1.52
  text "TEXAS INSTRUMENTS" at 129.87,-27.034 h1.52
M12 Stackup:
  lines w0.152: 288.544,189.484 353.314,189.484 ; 288.544,192.136 353.314,192.136 ; 287.02,177.165 ccw(c287.884,177.165) 287.884,176.301 353.974,176.301 ccw(c353.974,177.165) 354.838,177.165 354.838,195.097 ccw(c353.974,195.097) 353.974,195.961 287.884,195.961 ccw(c287.884,195.097) 287.02,195.097 287.02,177.165
  text "The Stackup Legend below this is static." at 294.78,200.012 h1.52
  text "If you change the stackup, update the Legend." at 295.034,197.726 h1.52
  text "Layer Stack Up Detail for: Ref_Design.PcbDoc" at 288.544,192.966 h1.45
  text "Layer" at 288.544,191.145 h0.61
  text "Gerber" at 311.298,191.145 h0.61
  text "Copper" at 325.611,191.145 h0.61
  text "Dielectric" at 340.92,191.145 h0.61
  text "Name" at 288.544,189.926 h0.61
  text "Document" at 311.298,189.926 h0.61
  text "Thickness" at 325.611,189.926 h0.61
  text "Material" at 340.92,189.926 h0.61
  text "Top Solder Mask" at 288.544,187.565 h0.86
  text "(.GTS)" at 311.298,187.565 h0.86
  text "Solder Resist" at 340.92,187.565 h0.86
  text "Top Layer" at 288.544,185.107 h0.86
  text "(.GTL)" at 311.298,185.107 h0.86
  text "1.4mil" at 325.611,185.107 h0.86
  text "FR-4" at 340.92,183.879 h0.86
  text "Bottom Layer" at 288.544,182.65 h0.86
  text "(.GBL)" at 311.298,182.65 h0.86
  text "1.4mil" at 325.611,182.65 h0.86
  text "Bottom Solder Mask" at 288.544,180.192 h0.86
  text "(.GBS)" at 311.298,180.192 h0.86
  text "Solder Resist" at 340.92,180.192 h0.86
  text ".Layer_Name" at 14.656,-21.806 h1.52
M13 Component Bodies Top:
  text ".Layer_Name" at 14.656,-21.806 h1.52
M14 Component Bodies Bottom:
  text ".Layer_Name" at 14.656,-21.806 h1.52
M15 Courtyards Top:
  text ".Layer_Name" at 14.656,-21.806 h1.52
M16 Courtyards Bottom:
  text ".Layer_Name" at 14.656,-21.806 h1.52
Drill Drawing:
  text ".legend" at 130.112,18.428 h1.52
  text "Drill Table" at 130.746,13.729 h1.52
  text ".Layer_Name" at 14.656,-21.806 h1.52

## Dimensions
0,55.118 to 78.74,52.578 on M2 Board Dimensions
80.772,52.07 to 80.01,0 on M2 Board Dimensions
